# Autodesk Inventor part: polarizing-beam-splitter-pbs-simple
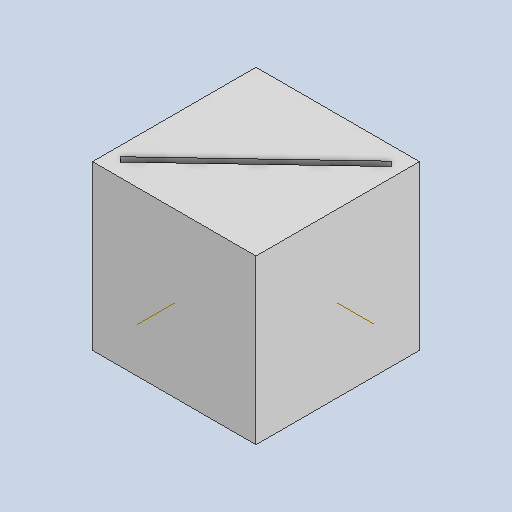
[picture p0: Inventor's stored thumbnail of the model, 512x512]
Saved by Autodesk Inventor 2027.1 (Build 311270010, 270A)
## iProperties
Created: 2026-07
Part Number: polarizing-beam-splitter-pbs-simple
Material: Generic
Document SubType Name: Modeling
Designer: dunge
Density: 1 g/cm^3
Appearance: Default
Author: dunge
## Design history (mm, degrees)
sketch "Sketch1"
  geometry: L1 (13.098, 13.251)-(13.97, 12.328); L2 (13.97, 12.328)-(-13.098, -13.251); L3 (-13.098, -13.251)-(-13.97, -12.328); L4 (-13.97, -12.328)-(13.098, 13.251); L5 (15.875, 15.875)-(-15.875, 15.875); L6 (-15.875, 15.875)-(-15.875, -15.875); L7 (-15.875, -15.875)-(15.875, -15.875); L8 (15.875, -15.875)-(15.875, 15.875); L9 (15.875, 15.875)-(-15.875, -15.875); L10 (-15.875, 15.875)-(15.875, -15.875); L11 (13.098, 13.251)-(-13.098, -13.251); L12 (13.97, 12.328)-(-13.97, -12.328); L13 (0, 9.79)-(0, -8.991); L14 (7.147, 0)-(-10.83, 0); 1 further point
  constraints: 28 end point, 4 parallel, 3 midpoint, 3 perpendicular, 2 horizontal, 1 point on line, 1 vertical
  dimensions: "CUBE_SIZE" = 31.75 distance of L5.end L6.end; "d2" = 1.27 distance of L2.end L3.end; "d6" = 1.905 distance from line of L8 L1.end
extrude "Extrusion1" new body sketch "Sketch1" stored distance "d4" = 31.75 (= CUBE_SIZE); taper "d5" = 0 deg
workpoint "Work Point1"
workaxis "Work Axis1"
workaxis "Work Axis2"
body "Solid1"
